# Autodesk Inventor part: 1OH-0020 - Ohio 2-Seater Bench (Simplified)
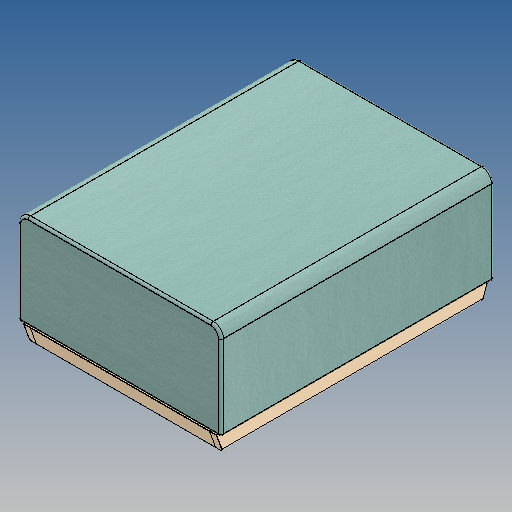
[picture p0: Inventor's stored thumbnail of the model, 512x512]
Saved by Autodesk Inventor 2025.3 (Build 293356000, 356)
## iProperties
Created: 2025-11
Part Number: 1OH-0020 - Ohio 2-Seater Bench (Simplified)
Material: Generic
Document SubType Name: Modeling
Designer: craig.ferris
Density: 1 g/cm^3
Appearance: CADET-ZEST SEAFOAM (219)
Author: craig.ferris
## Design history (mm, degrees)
body "Solid1"
body "Solid2"
body "Solid3"
body "Solid4"
body "Solid5"
body "Solid6"
body "Solid7"
body "Solid8"
body "Solid9"
body "Solid10"
body "Solid11"
body "Solid12"
body "Solid13"
body "Solid14"
body "Solid15"
